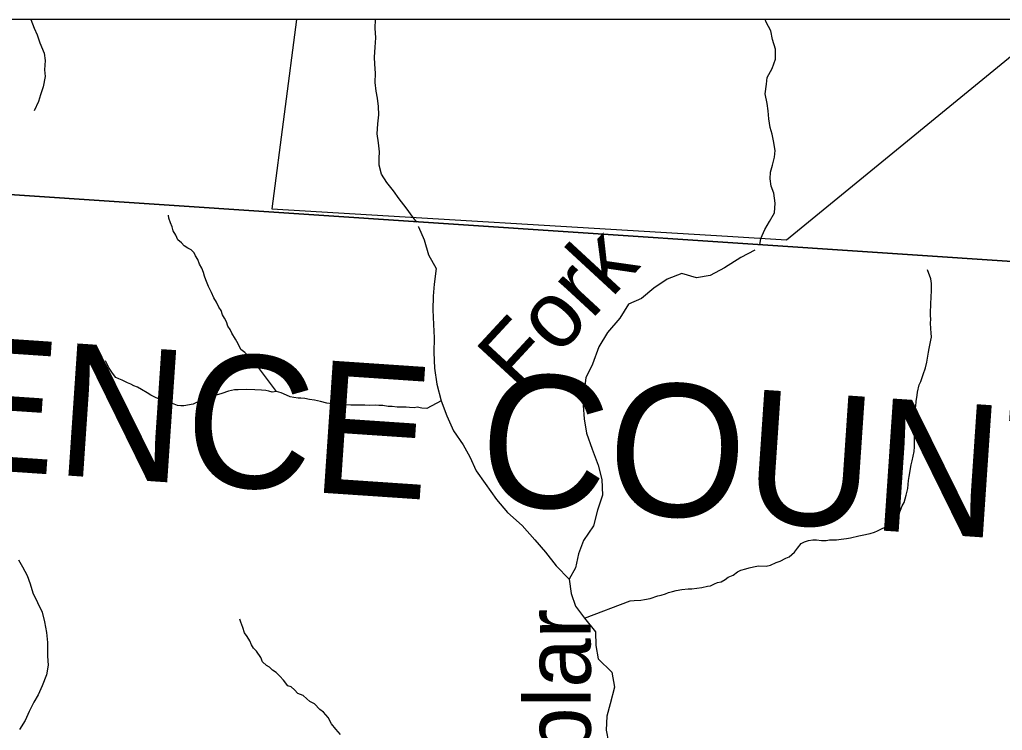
# Model space of a CAD drawing. Extents: x 0 to 44, y -23.8 to 22.
# Drawn here: x 4.614 to 6.018, y 19.884 to 20.9 of the extents above; entities that cross this region are included whole.
import ezdxf

# ---------------------------------------------------------------- set-up
doc = ezdxf.new("R2010")
doc.units = 0
for name, color, linetype in [('Default', 7, 'Continuous'), ('GM_X_County_Text', 7, 'Continuous'), ('GM_X_Minor_River', 7, 'Continuous'), ('GM_X_Minor_River_Text', 7, 'Continuous'), ('SH_Cut_Line', 7, 'Continuous')]:
    doc.layers.add(name, color=color, linetype=linetype)

msp = doc.modelspace()

# ---------------------------------------------------------------- linework, layer by layer
at = {"layer": 'Default'}
for points in [[(6.8158, 20.9), (2.3497, 20.9), (2.472, 20.6113), (2.8013, 19.8369), (3.0092, 19.3427), (3.0496, 19.2474), (3.1321, 19.0527), (3.1789, 18.9421), (3.455, 18.29), (3.5135, 19.1552), (3.5139, 19.1608), (3.5639, 19.9016), (3.5995, 20.4294), (3.5996, 20.4304), (3.6002, 20.4391), (3.6191, 20.7184), (3.9141, 20.6975), (4.3639, 20.6657), (6.7023, 20.5094), (6.7107, 20.5383)], [(6.0898, 20.9), (5.0097, 20.9), (4.9745, 20.6293), (5.6255, 20.5903), (5.7098, 20.5851), (6.0899, 20.8964)]]:
    msp.add_lwpolyline(points, close=True, dxfattribs=at)
msp.add_lwpolyline([(7.4495, 20.4611), (7.016, 20.4891), (6.892, 20.4972), (6.8124, 20.5023), (6.7257, 20.5079), (6.7023, 20.5094), (4.3639, 20.6657), (3.9141, 20.6975), (3.6191, 20.7184), (3.6002, 20.4391), (3.5996, 20.4304), (3.5995, 20.4294), (3.5639, 19.9016), (3.5139, 19.1608), (3.5135, 19.1552), (3.455, 18.29), (3.763, 17.5087), (3.7907, 17.4383), (4.026, 16.9163), (4.1422, 16.6361), (4.3476, 16.1408)], dxfattribs=at)
at = {"layer": 'GM_X_Minor_River'}
for points in [[(4.6302, 20.9), (4.6352, 20.8876), (4.6393, 20.8781), (4.6431, 20.8667), (4.6494, 20.8519), (4.6509, 20.8416), (4.6497, 20.828), (4.6505, 20.8185), (4.6478, 20.8037), (4.6439, 20.7927), (4.6413, 20.7829), (4.6348, 20.7696)], [(5.1817, 20.6106), (5.1767, 20.6173), (5.1665, 20.6307), (5.1567, 20.644), (5.1484, 20.6554), (5.139, 20.6672), (5.1314, 20.679), (5.1277, 20.6919), (5.1277, 20.7017), (5.1285, 20.7112), (5.1271, 20.7237), (5.1248, 20.7366), (5.126, 20.7511), (5.1276, 20.7639), (5.1269, 20.7757), (5.1254, 20.7878), (5.1235, 20.7977), (5.122, 20.8099), (5.1225, 20.8235), (5.1218, 20.8364), (5.1214, 20.8463), (5.1222, 20.8607), (5.123, 20.874), (5.1223, 20.8876), (5.1227, 20.9)], [(5.6718, 20.5779), (5.6732, 20.587), (5.6789, 20.5999), (5.6858, 20.6112), (5.6926, 20.6237), (5.6938, 20.6377), (5.692, 20.6518), (5.6882, 20.6617), (5.6864, 20.6723), (5.6868, 20.6821), (5.6898, 20.692), (5.6925, 20.7034), (5.6937, 20.7128), (5.6915, 20.7269), (5.6892, 20.7364), (5.6866, 20.7459), (5.6848, 20.7584), (5.6837, 20.7698), (5.6822, 20.78), (5.6792, 20.7937), (5.6811, 20.8077), (5.6823, 20.8172), (5.6896, 20.8301), (5.6941, 20.8437), (5.6942, 20.8577), (5.6897, 20.8714), (5.6875, 20.8839), (5.6807, 20.8965), (5.6794, 20.9)], [(4.981, 20.3683), (4.9467, 20.4139), (4.9406, 20.4189), (4.9358, 20.4243), (4.9301, 20.4286), (4.9264, 20.4366), (4.9227, 20.4431), (4.9175, 20.4519), (4.9149, 20.4569), (4.9119, 20.4615), (4.9097, 20.468), (4.9068, 20.4733), (4.9042, 20.4779), (4.9023, 20.484), (4.899, 20.489), (4.8956, 20.4959), (4.8919, 20.5024), (4.8882, 20.5097), (4.8841, 20.5185), (4.8823, 20.523), (4.8801, 20.528), (4.8782, 20.5334), (4.8768, 20.5383), (4.8746, 20.5448), (4.8712, 20.5506), (4.8686, 20.557), (4.8657, 20.5624), (4.8638, 20.5666), (4.8593, 20.5708), (4.8544, 20.5732), (4.8491, 20.5767), (4.8454, 20.5809), (4.8401, 20.5852), (4.8372, 20.5917), (4.8338, 20.5982), (4.832, 20.6039), (4.8298, 20.6096), (4.8276, 20.6161), (4.8269, 20.6203)], [(5.1835, 20.6044), (5.1839, 20.6037), (5.1922, 20.5851), (5.1985, 20.5638), (5.2093, 20.544), (5.2065, 20.522), (5.2049, 20.5045), (5.2044, 20.4851), (5.2054, 20.4639), (5.2064, 20.4449), (5.2059, 20.424), (5.2069, 20.4019), (5.2105, 20.3788), (5.2164, 20.3548), (5.2246, 20.3335), (5.2343, 20.3122), (5.2478, 20.292), (5.2576, 20.2748), (5.2665, 20.255), (5.2793, 20.2367), (5.2955, 20.2139), (5.3113, 20.1952), (5.3324, 20.1768), (5.3504, 20.1562), (5.3655, 20.1387), (5.3809, 20.1189), (5.3994, 20.0998), (5.4023, 20.0796), (5.4082, 20.0614), (5.4214, 20.0442), (5.4368, 20.0248), (5.4374, 20.005), (5.4407, 19.986), (5.4603, 19.9669), (5.4643, 19.9456), (5.4581, 19.9217), (5.453, 19.9039), (5.4522, 19.8842), (5.4555, 19.8671)], [(5.6647, 20.5705), (5.6444, 20.5599), (5.6215, 20.5452), (5.6006, 20.5343), (5.5813, 20.531), (5.5601, 20.5372), (5.5395, 20.529), (5.5201, 20.5161), (5.5029, 20.5014), (5.4839, 20.4932), (5.4716, 20.4731), (5.4541, 20.4527), (5.4418, 20.4322), (5.4325, 20.4076), (5.4233, 20.3879), (5.4205, 20.3663), (5.4192, 20.3484), (5.421, 20.3294), (5.4243, 20.3089), (5.4321, 20.2861), (5.4407, 20.2629), (5.4458, 20.2427), (5.4468, 20.2203), (5.4398, 20.1987), (5.434, 20.1763), (5.4198, 20.1555), (5.4129, 20.1362), (5.4082, 20.1161), (5.3994, 20.0998)], [(5.9086, 20.4021), (5.9102, 20.4104), (5.9127, 20.4245), (5.9139, 20.4298), (5.9159, 20.4415), (5.9171, 20.4461), (5.9164, 20.4522), (5.9161, 20.4579), (5.9158, 20.4666), (5.9159, 20.4712), (5.9156, 20.4776), (5.9156, 20.4829), (5.9161, 20.4913), (5.9167, 20.5057), (5.9171, 20.5103), (5.9172, 20.5171), (5.9169, 20.5228), (5.9162, 20.5293), (5.9114, 20.5423)], [(5.2164, 20.3548), (5.1959, 20.3439), (5.189, 20.3447), (5.1822, 20.3459), (5.1777, 20.3449), (5.1712, 20.3453), (5.1663, 20.3458), (5.1538, 20.3459), (5.1466, 20.3468), (5.1409, 20.3468), (5.1329, 20.3481), (5.1276, 20.3481), (5.1231, 20.349), (5.114, 20.3483), (5.1075, 20.3488), (5.1007, 20.3489), (5.0931, 20.349), (5.0874, 20.3487), (5.0802, 20.3491), (5.0749, 20.3496), (5.0662, 20.3501), (5.0609, 20.3509), (5.0533, 20.3514), (5.0442, 20.3541), (5.0397, 20.355), (5.0355, 20.3558), (5.0283, 20.357), (5.0215, 20.3582), (5.0162, 20.3587), (5.012, 20.3587), (5.006, 20.3596), (5.0007, 20.3608), (4.9954, 20.3631), (4.9878, 20.3666), (4.981, 20.3683), (4.975, 20.3672), (4.9704, 20.3688), (4.9659, 20.3696), (4.9598, 20.3704), (4.9503, 20.3709), (4.9378, 20.3711), (4.9264, 20.3705), (4.9211, 20.3709), (4.9128, 20.3687), (4.9032, 20.3654), (4.8952, 20.3629), (4.8899, 20.3603), (4.8853, 20.3588), (4.8792, 20.357), (4.8739, 20.3556), (4.867, 20.3526), (4.8621, 20.3504), (4.8488, 20.3479), (4.8446, 20.3476), (4.8397, 20.3484), (4.8302, 20.3519), (4.8253, 20.3535), (4.817, 20.3567), (4.8125, 20.3579), (4.8076, 20.3602), (4.8019, 20.3629), (4.7963, 20.3664), (4.7883, 20.3711), (4.7827, 20.3746), (4.7774, 20.3762), (4.7729, 20.3789), (4.7684, 20.3808), (4.7608, 20.3844), (4.7559, 20.3863), (4.7517, 20.3883), (4.7469, 20.3944), (4.7439, 20.399), (4.7413, 20.4032), (4.7394, 20.4074), (4.7368, 20.412)], [(5.4214, 20.0442), (5.4867, 20.0692), (5.492, 20.0695), (5.5019, 20.0698), (5.5068, 20.0709), (5.5152, 20.0723), (5.5262, 20.0763), (5.5308, 20.077), (5.5369, 20.0792), (5.5415, 20.0807), (5.5468, 20.0825), (5.5521, 20.084), (5.5605, 20.0854), (5.5696, 20.0864), (5.5745, 20.0863), (5.5818, 20.087), (5.589, 20.0881), (5.597, 20.0899), (5.6011, 20.0906), (5.6069, 20.0935), (5.6111, 20.095), (5.6164, 20.0964), (5.6221, 20.0994), (5.6263, 20.1028), (5.6336, 20.1057), (5.6401, 20.1106), (5.6447, 20.1128), (5.6519, 20.115), (5.6565, 20.1161), (5.6629, 20.1175), (5.6701, 20.1189), (5.6808, 20.1188), (5.6872, 20.1199), (5.6952, 20.1239), (5.7006, 20.1258), (5.709, 20.1302), (5.7135, 20.1317), (5.7212, 20.1384), (5.7258, 20.1441), (5.7308, 20.1512), (5.7358, 20.1535), (5.7415, 20.1553), (5.7476, 20.1563), (5.7529, 20.1563), (5.7597, 20.1554), (5.7665, 20.1553), (5.7715, 20.156), (5.7814, 20.1563), (5.7878, 20.157), (5.7954, 20.158), (5.8011, 20.1591), (5.8133, 20.162), (5.8182, 20.163), (5.8293, 20.1652), (5.8357, 20.1674), (5.8399, 20.1692), (5.8476, 20.1729), (5.8537, 20.1751), (5.8586, 20.1808), (5.8655, 20.1864), (5.8705, 20.1924), (5.8749, 20.2049), (5.8779, 20.2094), (5.8807, 20.22), (5.8831, 20.2295), (5.884, 20.2409), (5.8852, 20.2466), (5.8881, 20.2636), (5.8896, 20.2693), (5.8921, 20.2826), (5.8929, 20.289), (5.8926, 20.2932), (5.8927, 20.3039), (5.8928, 20.3084), (5.8925, 20.3153), (5.8929, 20.3194), (5.893, 20.3278), (5.8934, 20.332), (5.8939, 20.3434), (5.8947, 20.3475), (5.8952, 20.354), (5.8964, 20.3631), (5.8972, 20.3673), (5.8996, 20.3779), (5.902, 20.3824), (5.9051, 20.3926), (5.9086, 20.4021)], [(4.6128, 20.1277), (4.6185, 20.1174), (4.6249, 20.1052), (4.6293, 20.0933), (4.6331, 20.0804), (4.6398, 20.0667), (4.6462, 20.0526), (4.6499, 20.0392), (4.6524, 20.0236), (4.6539, 20.0095), (4.6538, 19.9997), (4.6541, 19.9898), (4.6548, 19.9769), (4.6524, 19.9632), (4.6462, 19.9473), (4.6408, 19.9348), (4.6343, 19.9242), (4.6277, 19.9109), (4.6219, 19.8977), (4.6139, 19.8852)], [(5.0725, 19.878), (5.0661, 19.8857), (5.0598, 19.893), (5.0549, 19.9022), (5.0482, 19.9099), (5.0429, 19.9137), (5.0354, 19.9218), (5.0287, 19.9253), (5.0245, 19.9288), (5.0193, 19.9338), (5.0117, 19.9365), (5.0068, 19.9419), (5.002, 19.9462), (4.9974, 19.9477), (4.9914, 19.9554), (4.9862, 19.9612), (4.9809, 19.9666), (4.9757, 19.9701), (4.9712, 19.9743), (4.967, 19.9766), (4.9614, 19.9816), (4.9588, 19.9878), (4.9525, 19.997), (4.9483, 20.0012), (4.9457, 20.0062), (4.9432, 20.0119), (4.9394, 20.018), (4.9357, 20.0234), (4.9331, 20.031), (4.9302, 20.0387), (4.9287, 20.0429)]]:
    msp.add_lwpolyline(points, dxfattribs=at)
at = {"layer": 'SH_Cut_Line'}
for points in [[(4.3476, 16.1408), (4.1422, 16.6361), (4.026, 16.9163), (3.7907, 17.4383), (3.763, 17.5087), (3.455, 18.29), (3.5135, 19.1552), (3.5139, 19.1608), (3.5639, 19.9016), (3.5995, 20.4294), (3.5996, 20.4304), (3.6002, 20.4391), (3.6191, 20.7184), (3.9141, 20.6975), (4.3639, 20.6657), (6.7023, 20.5094), (6.7107, 20.5383), (6.8158, 20.9), (2.1, 20.9), (2.1, 14.1)], [(8.9, 20.9), (6.8158, 20.9), (6.7107, 20.5383), (6.7023, 20.5094), (4.3639, 20.6657), (3.9141, 20.6975), (3.6191, 20.7184), (3.6002, 20.4391), (3.5996, 20.4304), (3.5995, 20.4294), (3.5639, 19.9016), (3.5139, 19.1608), (3.5135, 19.1552), (3.455, 18.29), (3.763, 17.5087), (3.7907, 17.4383), (4.026, 16.9163), (4.1422, 16.6361), (4.3476, 16.1408)]]:
    msp.add_lwpolyline(points, dxfattribs=at)

# ---------------------------------------------------------------- texts
at = {"layer": 'GM_X_County_Text'}
msp.add_text('LAWRENCE COUNTY', height=0.189394, rotation=356.1322, dxfattribs=at).set_placement((3.7646, 20.3102))
at = {"layer": 'GM_X_Minor_River_Text'}
for s, rotation, p in [('Fork', 47.2684, (5.3308, 20.3615)), ('Poplar', 89.9998, (5.4302, 19.6913))]:
    msp.add_text(s, height=0.0947, rotation=rotation, dxfattribs=at).set_placement(p)

doc.saveas('drawing.dxf')
